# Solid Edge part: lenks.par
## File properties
Title: lenks
Author: Stella-Marii
Template: iso metric part.par
Last saved by: Stella-Marii
Revision: 6
Application: Solid Edge
Document Number: 21
Density: 7833,000 kg/m^3
Accuracy: 0,990
Username: Stella-Marii
Material: Steel, structural
Face Style: Steel
Fill Style: ANSI32(Steel)
Virtual Style: Brushed steel
Grouping: Metals\Steel
LibraryName: Materials
Coef. of Thermal Exp: 1.3e-05
Thermal Conductivity: 32.0
Specific Heat: 481.0
Modulus of Elasticity: 199947953000.0
Poisson's Ratio: 0.29
Yield Stress: 262000766.0
Ultimate Stress: 358527364.0
Elongation: 0.0
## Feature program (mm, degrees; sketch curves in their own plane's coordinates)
sketch for "unnamed Protrusion 1" plane through (0, 0, 0) normal (0, -1, 0) x-axis (1, 0, 0)
  circle centre (0, 0) radius 12.5
extrude "unnamed Protrusion 1" add finite 550 symmetric
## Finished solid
Body 1: solid body, 3 faces, 2 edges, 0 vertices.
  Faces by surface: plane 2, cylinder 1
  Edges by curve: circle 2
Bounding box of the edges (mm): 25.000 x 550.000 x 25.000, from (-12.5, -275, -12.5) to (12.5, 275, 12.5).
Cylindrical faces by radius (mm): R12.5 x1
Planar faces by outward normal: +y 1, -y 1
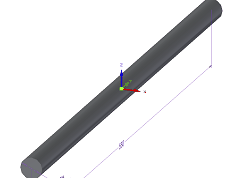
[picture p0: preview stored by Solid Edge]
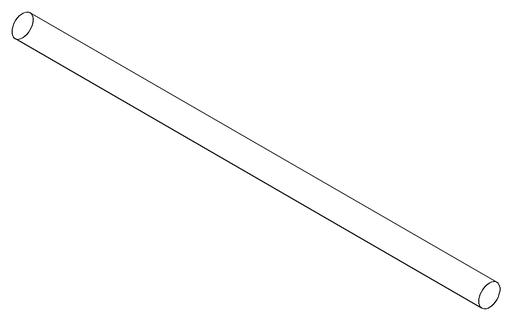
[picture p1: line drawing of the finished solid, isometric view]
